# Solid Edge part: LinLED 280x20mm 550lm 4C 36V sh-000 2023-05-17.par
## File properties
Author: jaroslaw.przewlocki
Template: iso metric part.par
Last saved by: jaroslaw.przewlocki
Revision: 1
Application: Solid Edge
Gęstość: 0,000 kg/m^3
Dokładność: 0,990
Username: jaroslaw.przewlocki
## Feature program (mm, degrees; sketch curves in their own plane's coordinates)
body "unnamed Body 1"
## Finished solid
Body 1: solid body, 1190 faces, 3032 edges, 1904 vertices.
  Faces by surface: plane 599, cylinder 279, torus 128, cone 100, spline 52, sphere 32
  Edges by curve: line 1778, curve on surface 712, circle 338, ellipse 132, spline 72
Bounding box of the edges (mm; curved faces can reach further): 279.600 x 20.000 x 4.450, from (-139.8, -10, 0) to (139.8, 10, 4.45).
Cylindrical faces by radius (mm): R0.2 x92, R0.2169 x12, R0.25 x34, R0.3373 x12, R0.4 x16, R0.4006 x4, R0.4008 x4, R0.525 x4, R0.6 x40, R1 x20, R1.1 x8, R1.1989 x4, R1.199 x4, R1.2 x20, R2.15 x5
Conical faces (half-angle, radius in mm at the cone's reference point): 0.398 deg R1.1964 x4, 0.4493 deg R1.1964 x4, 0.4746 deg R1.1948 x4, 0.4758 deg R1.1948 x4, 0.5 deg R0.5056 x8, 0.5 deg R1.0082 x8, 1 deg R0.5511 x4, 10 deg R0.2132 x8, 10 deg R0.4132 x8, 16.0099 deg R1.1053 x4, 16.1249 deg R1.1279 x4, 18.8604 deg R1.0669 x8, 19.5041 deg R0.5138 x4, 19.8244 deg R0.5099 x4, 27.363 deg R0.6214 x4, 40.6434 deg R0.5161 x4, 43.3309 deg R0.4892 x4, 45 deg R0.575 x4, 45 deg R0.625 x8
Toroidal faces (ring radius, tube radius in mm): R0.0958 r0.3997 x8, R0.1076 r0.4 x4, R0.1101 r0.4001 x4, R0.1217 r0.4 x4, R0.1234 r0.4 x4, R0.1626 r0.228 x4, R0.1634 r0.2287 x4, R0.3287 r0.2001 x4, R0.3684 r0.2151 x4, R0.3703 r0.4 x4, R0.3818 r0.2 x8, R0.4166 r0.3983 x4, R0.5981 r0.197 x4, R0.5982 r0.197 x4, R0.6009 r0.3968 x4, R0.6009 r0.3969 x4, R0.6227 r0.2 x4, R0.6235 r0.2 x4, R0.8 r0.2 x8, R0.8522 r0.3 x4, R0.9002 r0.2 x4, R0.9018 r0.2 x4, R0.9197 r0.223 x4, R0.9365 r0.2 x4, R0.9663 r0.2263 x4, R0.9665 r0.2263 x4, R1.429 r1.2 x4, R1.8741 r0.2175 x4, R1.9007 r0.2 x4
Spherical faces by radius (mm): R0.2 x24, R0.6 x8
Planar faces by outward normal: +x 60, +y 64, +z 85, -x 60, -y 65, -z 17, oblique 248
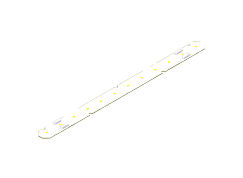
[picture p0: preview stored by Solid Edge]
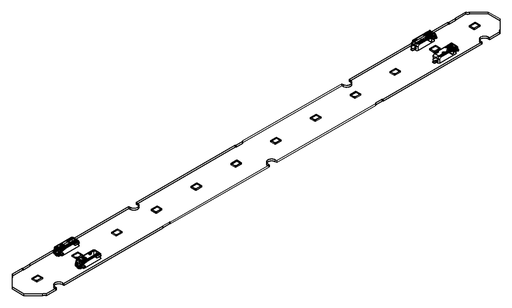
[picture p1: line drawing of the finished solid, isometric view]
